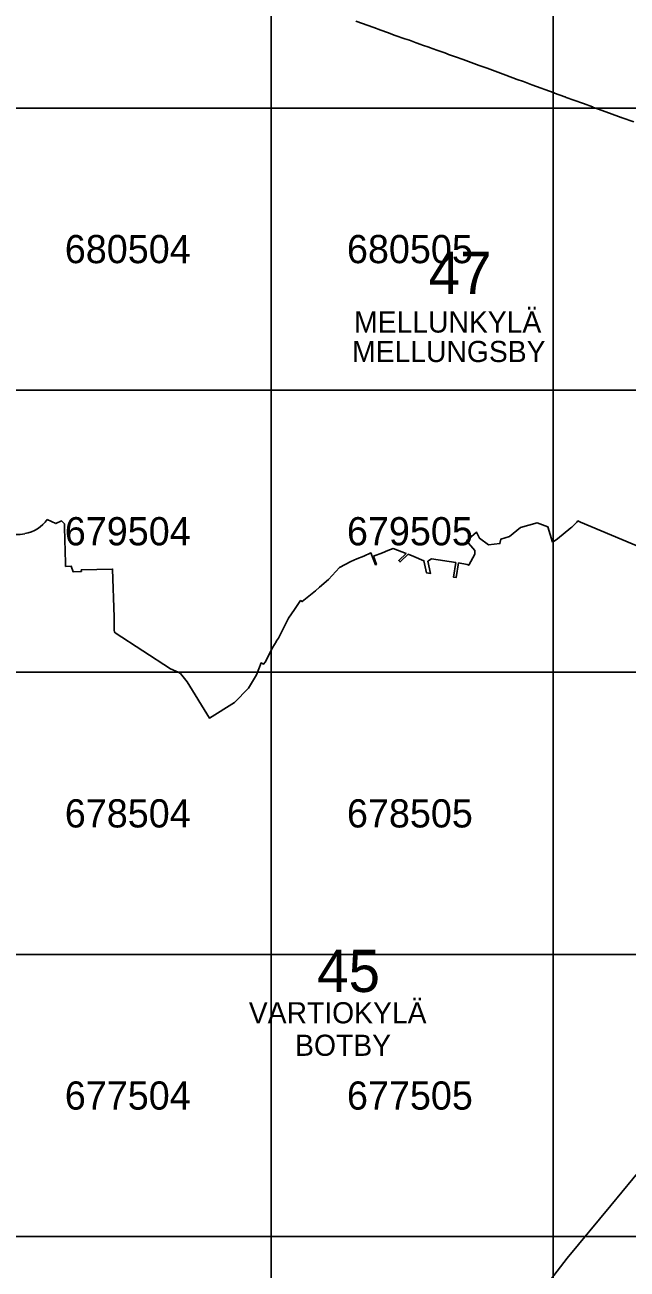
# Model space of a CAD drawing. Extents: x 25485000 to 25520000, y 6656775 to 6690000.
# Drawn here: x 25504127 to 25506262, y 6676885 to 6681295 of the extents above; entities that cross this region are included whole.
import ezdxf

# ---------------------------------------------------------------- set-up
doc = ezdxf.new("R2010")
doc.units = 0
doc.layers.add('Level 63', color=7, linetype='Continuous')

msp = doc.modelspace()

# ---------------------------------------------------------------- linework, layer by layer
at = {"layer": 'Level 63'}
for points in [[(25504000, 6681000), (25505000, 6681000), (25505000, 6682000), (25504000, 6682000)], [(25505000, 6681000), (25506000, 6681000), (25506000, 6682000), (25505000, 6682000)], [(25506000, 6681000), (25507000, 6681000), (25507000, 6682000), (25506000, 6682000)], [(25504000, 6680000), (25505000, 6680000), (25505000, 6681000), (25504000, 6681000)], [(25505000, 6680000), (25506000, 6680000), (25506000, 6681000), (25505000, 6681000)], [(25506000, 6680000), (25507000, 6680000), (25507000, 6681000), (25506000, 6681000)], [(25504000, 6679000), (25505000, 6679000), (25505000, 6680000), (25504000, 6680000)], [(25505000, 6679000), (25506000, 6679000), (25506000, 6680000), (25505000, 6680000)], [(25506000, 6679000), (25507000, 6679000), (25507000, 6680000), (25506000, 6680000)], [(25504000, 6678000), (25505000, 6678000), (25505000, 6679000), (25504000, 6679000)], [(25505000, 6678000), (25506000, 6678000), (25506000, 6679000), (25505000, 6679000)], [(25506000, 6678000), (25507000, 6678000), (25507000, 6679000), (25506000, 6679000)], [(25504000, 6677000), (25505000, 6677000), (25505000, 6678000), (25504000, 6678000)], [(25505000, 6677000), (25506000, 6677000), (25506000, 6678000), (25505000, 6678000)], [(25506000, 6677000), (25507000, 6677000), (25507000, 6678000), (25506000, 6678000)], [(25504000, 6676000), (25505000, 6676000), (25505000, 6677000), (25504000, 6677000)], [(25505000, 6676000), (25506000, 6676000), (25506000, 6677000), (25505000, 6677000)], [(25506000, 6676000), (25507000, 6676000), (25507000, 6677000), (25506000, 6677000)]]:
    msp.add_lwpolyline(points, close=True, dxfattribs=at)
for points in [[(25505300.4, 6681307.6), (25505363.7, 6681285), (25505388.2, 6681276.1), (25505412.7, 6681267.3), (25505439.9, 6681257.6), (25505447, 6681255.2), (25505466.6, 6681248.1), (25505473.5, 6681245.6), (25505489.8, 6681239.9), (25505501.9, 6681235.4), (25505513.3, 6681231.4), (25505530.2, 6681225.1), (25505536.7, 6681222.7), (25505558.5, 6681215.1), (25505560.6, 6681214.5), (25505587, 6681205), (25505615.2, 6681195), (25505623.7, 6681191.6), (25505627.9, 6681190.2), (25505652.7, 6681181.5), (25505681, 6681171.5), (25505709.2, 6681161.2), (25505737.4, 6681150.8), (25505765.7, 6681140.7), (25505793.6, 6681130.6), (25505821.8, 6681120.1), (25505856.3, 6681107.3), (25505871.3, 6681101.6), (25505893.7, 6681093.4), (25505924, 6681082.4), (25506002.6, 6681053.7), (25506004.5, 6681052.9), (25506040.2, 6681040), (25506041.7, 6681039.5), (25506045.9, 6681037.8), (25506072.6, 6681028.1), (25506106.6, 6681015.7), (25506139.2, 6681003.8), (25506142.9, 6681002.4), (25506156.1, 6680997.6), (25506198.5, 6680982.2), (25506240.9, 6680966.7), (25506242.2, 6680966.2), (25506243.7, 6680965.7), (25506285, 6680950.6)], [(25504443, 6679147.7), (25504443, 6679195.6), (25504438.1, 6679366), (25504327.1, 6679362.8), (25504327.3, 6679357.5), (25504297.9, 6679356.5), (25504291.5, 6679375.8), (25504271.5, 6679375.2), (25504269.7, 6679441.2), (25504269.2, 6679458.2), (25504267.2, 6679526.7), (25504256.9, 6679536.4), (25504236.2, 6679526.8), (25504206, 6679541.4)], [(25504443, 6679147.7), (25504443, 6679195.6), (25504438.1, 6679366), (25504327.1, 6679362.8), (25504327.3, 6679357.5), (25504297.9, 6679356.5), (25504291.5, 6679375.8), (25504271.5, 6679375.2), (25504269.7, 6679441.2), (25504269.2, 6679458.2), (25504267.2, 6679526.7), (25504256.9, 6679536.4), (25504236.2, 6679526.8), (25504206, 6679541.4)], [(25506558.1, 6679338.5), (25506096.7, 6679532.6), (25506087.1, 6679536.7), (25506083.6, 6679532.7), (25506080.2, 6679528.9), (25506076.7, 6679525.2), (25506072.6, 6679521.2), (25506068.8, 6679517.7), (25506065.3, 6679514.6), (25506062.1, 6679511.9), (25506015.3, 6679473.4), (25506014.7, 6679472.9), (25506006.2, 6679466.7), (25505997.1, 6679461.5), (25505981, 6679515.3), (25505942.3, 6679530.3), (25505883.5, 6679512.8), (25505845.2, 6679481.7), (25505813.9, 6679471.8), (25505810.6, 6679456.3), (25505770.8, 6679451.7), (25505738.5, 6679475), (25505728.1, 6679496.5), (25505700.8, 6679472.8), (25505692.5, 6679465.6), (25505721.9, 6679431.8), (25505722.2, 6679419.1), (25505700.4, 6679379.5), (25505695.1, 6679382.4), (25505664, 6679387.4), (25505655.8, 6679336.1), (25505645.9, 6679337.7), (25505654.1, 6679389), (25505568.1, 6679401.7), (25505555.7, 6679393.8), (25505565.2, 6679350.4), (25505551, 6679352.6), (25505550.5, 6679352), (25505541.1, 6679395.2), (25505505.1, 6679410.5), (25505485.9, 6679418.6), (25505456.7, 6679391.1), (25505451.9, 6679396.2), (25505478.1, 6679420.9), (25505432.9, 6679438.4), (25505413.8, 6679431.2), (25505394, 6679423.7), (25505362.2, 6679411.7), (25505373.2, 6679382.6), (25505370, 6679381.2), (25505353.7, 6679423.1), (25505328, 6679412.1), (25505304.1, 6679401.9), (25505282, 6679392.5), (25505242.5, 6679372), (25505203.6, 6679328.8), (25505171.5, 6679301.3), (25505157.3, 6679288.6), (25505110.2, 6679250.5), (25505104, 6679254.2), (25505082.3, 6679222.4), (25505061.6, 6679192), (25505025.4, 6679121.3), (25505019.4, 6679111.4), (25505017.7, 6679108.5), (25505005.7, 6679088.9), (25504997.6, 6679073.2), (25504982.9, 6679044.1), (25504978.9, 6679036.2), (25504972.5, 6679028.5), (25504964.4, 6679033.2), (25504947.8, 6678990.9), (25504919.6, 6678944.1), (25504870.2, 6678892.8), (25504781.1, 6678837.7), (25504701.9, 6678965.8), (25504678, 6678995.4), (25504670.6, 6679000.6), (25504642.7, 6679011.8), (25504447.6, 6679139.4)], [(25506558.1, 6679338.5), (25506096.7, 6679532.6), (25506087.1, 6679536.7), (25506083.6, 6679532.7), (25506080.2, 6679528.9), (25506076.7, 6679525.2), (25506072.6, 6679521.2), (25506068.8, 6679517.7), (25506065.3, 6679514.6), (25506062.1, 6679511.9), (25506015.3, 6679473.4), (25506014.7, 6679472.9), (25506006.2, 6679466.7), (25505997.1, 6679461.5), (25505981, 6679515.3), (25505942.3, 6679530.3), (25505883.5, 6679512.8), (25505845.2, 6679481.7), (25505813.9, 6679471.8), (25505810.6, 6679456.3), (25505770.8, 6679451.7), (25505738.5, 6679475), (25505728.1, 6679496.5), (25505700.8, 6679472.8), (25505692.5, 6679465.6), (25505721.9, 6679431.8), (25505722.2, 6679419.1), (25505700.4, 6679379.5), (25505695.1, 6679382.4), (25505664, 6679387.4), (25505655.8, 6679336.1), (25505645.9, 6679337.7), (25505654.1, 6679389), (25505568.1, 6679401.7), (25505555.7, 6679393.8), (25505565.2, 6679350.4), (25505551, 6679352.6), (25505550.5, 6679352), (25505541.1, 6679395.2), (25505505.1, 6679410.5), (25505485.9, 6679418.6), (25505456.7, 6679391.1), (25505451.9, 6679396.2), (25505478.1, 6679420.9), (25505432.9, 6679438.4), (25505413.8, 6679431.2), (25505394, 6679423.7), (25505362.2, 6679411.7), (25505373.2, 6679382.6), (25505370, 6679381.2), (25505353.7, 6679423.1), (25505328, 6679412.1), (25505304.1, 6679401.9), (25505282, 6679392.5), (25505242.5, 6679372), (25505203.6, 6679328.8), (25505171.5, 6679301.3), (25505157.3, 6679288.6), (25505110.2, 6679250.5), (25505104, 6679254.2), (25505082.3, 6679222.4), (25505061.6, 6679192), (25505025.4, 6679121.3), (25505019.4, 6679111.4), (25505017.7, 6679108.5), (25505005.7, 6679088.9), (25504997.6, 6679073.2), (25504982.9, 6679044.1), (25504978.9, 6679036.2), (25504972.5, 6679028.5), (25504964.4, 6679033.2), (25504947.8, 6678990.9), (25504919.6, 6678944.1), (25504870.2, 6678892.8), (25504781.1, 6678837.7), (25504701.9, 6678965.8), (25504678, 6678995.4), (25504670.6, 6679000.6), (25504642.7, 6679011.8), (25504447.6, 6679139.4)], [(25506321.3, 6677251.8), (25506203.7, 6677109.7), (25506049.4, 6676923.5), (25505887.3, 6676713.1), (25505815.7, 6676624.4), (25505811, 6676618.2), (25505576.6, 6676232), (25505550.7, 6676189.2), (25505535.7, 6676164.4), (25505465.4, 6676048), (25505444.7, 6676013.7), (25505402.6, 6675943.9), (25505360.4, 6675873.9), (25505248.6, 6675730.3), (25504991.1, 6675470.2), (25504941.6, 6675420.2), (25504854.1, 6675200.3), (25504837.4, 6674871.4), (25505612.3, 6674222.2), (25506247.7, 6673689.9), (25506181.2, 6673225), (25505895.6, 6672754.3), (25506849.3, 6672473)], [(25505887.3, 6676713.1), (25506049.4, 6676923.5), (25506203.7, 6677109.7), (25506321.3, 6677251.8)]]:
    msp.add_lwpolyline(points, dxfattribs=at)
for centre, radius, start, end in [((25504104.5, 6679614.3), 125, 280.4079, 324.3473), ((25504104.5, 6679614.3), 125, 280.4078, 324.3473), ((25504090.9, 6679688), 200, 261.6019, 280.4079), ((25504090.9, 6679688), 200, 261.6021, 280.4079), ((25504453, 6679147.7), 10, 180.1017, 236.8288), ((25504453, 6679147.7), 10, 180.1036, 236.8282)]:
    msp.add_arc(centre, radius, start, end, dxfattribs=at)

# ---------------------------------------------------------------- texts
for s, height, p in [('680504', 100, (25504268.5, 6680450)), ('680505', 100, (25505268.5, 6680450)), ('47', 150, (25505557.7, 6680340.5)), ('MELLUNKYLÄ', 75, (25505294, 6680204.1)), ('MELLUNGSBY', 75, (25505286.8, 6680099.6)), ('679504', 100, (25504268.5, 6679450)), ('679505', 100, (25505268.5, 6679450)), ('678504', 100, (25504268.5, 6678450)), ('678505', 100, (25505268.5, 6678450)), ('45', 150, (25505162.7, 6677866.8)), ('VARTIOKYLÄ', 75, (25504920.7, 6677755.8)), ('BOTBY', 75, (25505084.8, 6677640.6)), ('677504', 100, (25504268.5, 6677450)), ('677505', 100, (25505268.5, 6677450))]:
    msp.add_text(s, height=height, dxfattribs=at).set_placement(p)

doc.saveas('drawing.dxf')
